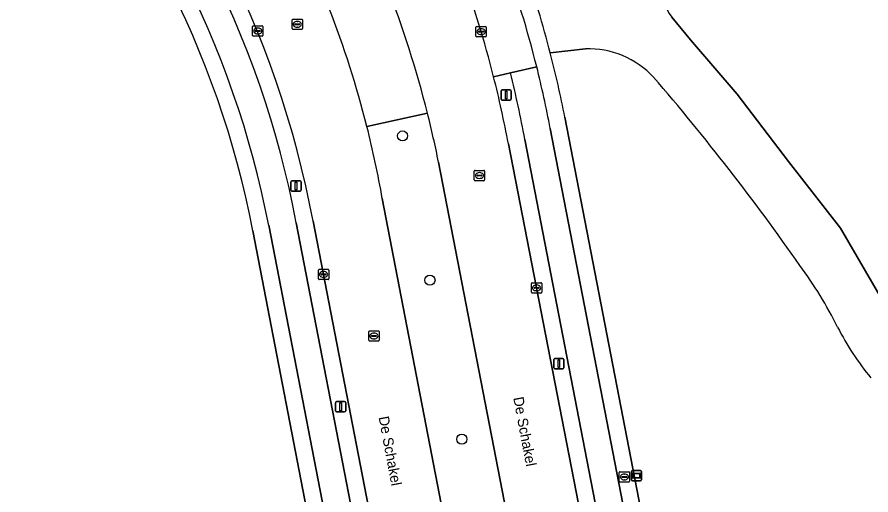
# Model space of a CAD drawing. Extents: x 156141 to 158132, y 385651 to 388333.
# Drawn here: x 156763.2 to 156845.9, y 386839.7 to 386886.1 of the extents above; entities that cross this region are included whole.
import ezdxf

# ---------------------------------------------------------------- set-up
doc = ezdxf.new("R2010")
doc.units = 0
for name, color, linetype in [('IMGEO_Berm_groen', 7, 'Continuous'), ('IMGEO_Boom', 7, 'Continuous'), ('IMGEO_Brandkraan', 7, 'Continuous'), ('IMGEO_Erf', 7, 'Continuous'), ('IMGEO_Fietspad_gesloten', 7, 'Continuous'), ('IMGEO_Kolk', 7, 'Continuous'), ('IMGEO_Lichtmast', 7, 'Continuous'), ('IMGEO_Openbare_ruimte_label', 7, 'Continuous'), ('IMGEO_Rijbaan_lokaal_gesloten', 7, 'Continuous'), ('IMGEO_Rijbaan_lokaal_open', 7, 'Continuous'), ('IMGEO_Rioolput', 7, 'Continuous'), ('IMGEO_Verklikker', 7, 'Continuous'), ('IMGEO_Voetpad_open', 7, 'Continuous')]:
    doc.layers.add(name, color=color, linetype=linetype)

msp = doc.modelspace()

# ---------------------------------------------------------------- linework, layer by layer
at = {"layer": 'IMGEO_Berm_groen'}
for points in [[(156810.993, 386880.684), (156809.365, 386880.309)], [(156802.956, 386876.762), (156797.082, 386875.477)], [(156810.794, 386873.793), (156823.671, 386807.616), (156825.217, 386807.909), (156812.389, 386874.233)], [(156798.576, 386868.484), (156810.203, 386808.253), (156816.188, 386809.335), (156804.032, 386872.006)], [(156790.238, 386866.122), (156802.323, 386803.676), (156803.921, 386803.962), (156791.866, 386866.288)]]:
    msp.add_lwpolyline(points, dxfattribs=at)
for centre, radius, start, end in [((156697.171, 386848.541), 96.344, 10.61478, 43.91153), ((156697.735, 386848.719), 94.126, 10.65483, 44.23031), ((156710.398, 386855.539), 103.69, 10.38669, 14.03443), ((156709.21, 386854.93), 103.32, 10.51953, 14.21947), ((156702.267, 386851.482), 103.814, 11.40228, 14.09375), ((156702.296, 386851.571), 97.754, 9.96341, 14.15559)]:
    msp.add_arc(centre, radius, start, end, dxfattribs=at)
at = {"layer": 'IMGEO_Boom'}
for centre in [(156800.541, 386874.566), (156803.195, 386860.57), (156806.282, 386845.15)]:
    msp.add_circle(centre, 0.489, dxfattribs=at)
at = {"layer": 'IMGEO_Brandkraan'}
for p, q in [((156821.54, 386841.068), (156821.54, 386841.92)), ((156821.615, 386841.994), (156822.467, 386841.994)), ((156821.799, 386841.488), (156821.799, 386841.5)), ((156821.842, 386841.537), (156822.24, 386841.537)), ((156822.028, 386841.774), (156822.053, 386841.774)), ((156822.283, 386841.5), (156822.283, 386841.488)), ((156822.541, 386841.92), (156822.541, 386841.068)), ((156822.467, 386840.994), (156821.615, 386840.994)), ((156822.237, 386841.451), (156821.839, 386841.451)), ((156822.051, 386841.214), (156822.026, 386841.214))]:
    msp.add_line(p, q, dxfattribs=at)
for points in [[(156821.54, 386841.068), (156821.54, 386841.92)], [(156821.615, 386841.994), (156822.467, 386841.994)], [(156822.541, 386841.92), (156822.541, 386841.068)], [(156822.467, 386840.994), (156821.615, 386840.994)]]:
    msp.add_lwpolyline(points, dxfattribs=at)
for centre, radius, start, end in [((156821.617, 386841.918), 0.0765, 91.55205, 178.44795), ((156821.617, 386841.918), 0.0765, 91.55205, 178.44795), ((156821.839, 386841.497), 0.0403, 85.87752, 175.75265), ((156821.836, 386841.487), 0.0366, 178.93798, 274.71019), ((156822.24, 386841.494), 0.043, 264.86636, 352.45326), ((156822.244, 386841.499), 0.0386, 1.73085, 96.63898), ((156822.465, 386841.918), 0.0765, 1.55205, 88.44795), ((156822.465, 386841.918), 0.0765, 1.55205, 88.44795), ((156821.617, 386841.07), 0.0765, 181.55205, 268.44795), ((156821.617, 386841.07), 0.0765, 181.55205, 268.44795), ((156822.465, 386841.07), 0.0765, 271.55205, 358.44795), ((156822.465, 386841.07), 0.0765, 271.55205, 358.44795)]:
    msp.add_arc(centre, radius, start, end, dxfattribs=at)
for centre, major_axis, ratio, start_param, end_param in [((156822.027, 386841.494), (-0.387, 0.002), 0.722429, 4.712389, 7.853982), ((156822.052, 386841.494), (-0.39, 0.002), 0.717154, 1.570796, 4.712389)]:
    msp.add_ellipse(centre, major_axis=major_axis, ratio=ratio, start_param=start_param, end_param=end_param, dxfattribs=at)
at = {"layer": 'IMGEO_Erf'}
for points in [[(156826.636, 386886.092), (156828.456, 386883.873), (156832.982, 386878.607), (156837.967, 386872.098), (156842.982, 386865.604), (156848.662, 386855.9)], [(156818.263, 386883.015), (156814.86, 386882.608)], [(156816.275, 386876.382), (156829.265, 386809.226), (156830.26, 386804.068), (156832.909, 386790.329), (156833.43, 386787.629), (156834.864, 386780.192), (156835.335, 386777.724), (156835.579, 386776.447), (156836.335, 386772.49), (156839.986, 386753.519), (156840.741, 386750), (156841.955, 386745.365)], [(156789.25, 386785.838), (156797.816, 386791.602), (156799.862, 386793.67), (156786.023, 386865.361)]]:
    msp.add_lwpolyline(points, dxfattribs=at)
for centre, radius, start, end in [((156696.676, 386848.251), 90.971, 10.84103, 44.16358), ((156830.262, 386888.804), 4.528, 133.86718, 216.79599), ((156818.511, 386874.287), 8.732, 43.19971, 91.62579), ((156711.598, 386855.865), 106.669, 11.08926, 14.51927), ((156650.564, 386730.314), 229.935, 34.94261, 40.70341), ((156805.973, 386837.682), 41.058, 26.50354, 36.33706), ((156866.609, 386868.18), 26.816, 207.00334, 219.5816)]:
    msp.add_arc(centre, radius, start, end, dxfattribs=at)
at = {"layer": 'IMGEO_Fietspad_gesloten'}
for points in [[(156813.544, 386881.272), (156810.993, 386880.684)], [(156827.767, 386808.488), (156814.851, 386875.299)], [(156812.389, 386874.233), (156825.217, 386807.909), (156825.43, 386807.901), (156825.634, 386806.897), (156826.277, 386803.502), (156826.472, 386802.55), (156826.249, 386802.491), (156828.033, 386793.229)], [(156787.566, 386865.893), (156800.014, 386801.586), (156802.367, 386802.045), (156802.289, 386802.533), (156802.117, 386803.516), (156802.323, 386803.676), (156790.238, 386866.122)]]:
    msp.add_lwpolyline(points, dxfattribs=at)
for centre, radius, start, end in [((156697.735, 386848.719), 94.126, 10.65483, 44.23031), ((156696.985, 386848.39), 92.256, 10.93627, 43.98113), ((156711.691, 386855.855), 104.977, 10.67398, 14.01163), ((156710.398, 386855.539), 103.69, 10.38669, 14.03443)]:
    msp.add_arc(centre, radius, start, end, dxfattribs=at)
at = {"layer": 'IMGEO_Kolk'}
for p, q in [((156786.008, 386884.32), (156786.008, 386885.172)), ((156786.083, 386885.246), (156786.935, 386885.246)), ((156786.267, 386884.74), (156786.267, 386884.752)), ((156786.705, 386884.703), (156786.307, 386884.703)), ((156786.31, 386884.789), (156786.708, 386884.789)), ((156786.496, 386885.026), (156786.521, 386885.026)), ((156786.751, 386884.752), (156786.751, 386884.74)), ((156787.009, 386885.172), (156787.009, 386884.32)), ((156807.654, 386884.252), (156807.654, 386885.104)), ((156807.729, 386885.178), (156808.581, 386885.178)), ((156807.913, 386884.672), (156807.913, 386884.684)), ((156808.351, 386884.635), (156807.953, 386884.635)), ((156807.956, 386884.721), (156808.354, 386884.721)), ((156808.142, 386884.958), (156808.167, 386884.958)), ((156808.397, 386884.684), (156808.397, 386884.672)), ((156808.655, 386885.104), (156808.655, 386884.252)), ((156786.935, 386884.246), (156786.083, 386884.246)), ((156786.519, 386884.466), (156786.494, 386884.466)), ((156808.581, 386884.178), (156807.729, 386884.178)), ((156808.165, 386884.398), (156808.14, 386884.398)), ((156792.385, 386860.705), (156792.385, 386861.557)), ((156792.46, 386861.631), (156793.312, 386861.631)), ((156792.873, 386861.411), (156792.898, 386861.411)), ((156793.386, 386861.557), (156793.386, 386860.705)), ((156793.312, 386860.631), (156792.46, 386860.631)), ((156792.644, 386861.125), (156792.644, 386861.137)), ((156793.082, 386861.088), (156792.684, 386861.088)), ((156792.687, 386861.174), (156793.085, 386861.174)), ((156792.896, 386860.851), (156792.871, 386860.851)), ((156793.128, 386861.137), (156793.128, 386861.125)), ((156813.032, 386859.401), (156813.032, 386860.253)), ((156813.107, 386860.327), (156813.959, 386860.327)), ((156813.291, 386859.821), (156813.291, 386859.833)), ((156813.729, 386859.784), (156813.331, 386859.784)), ((156813.334, 386859.87), (156813.732, 386859.87)), ((156813.52, 386860.107), (156813.545, 386860.107)), ((156813.775, 386859.833), (156813.775, 386859.821)), ((156814.033, 386860.253), (156814.033, 386859.401)), ((156813.959, 386859.327), (156813.107, 386859.327)), ((156813.543, 386859.547), (156813.518, 386859.547))]:
    msp.add_line(p, q, dxfattribs=at)
for points in [[(156786.008, 386884.32), (156786.008, 386885.172)], [(156786.083, 386885.246), (156786.935, 386885.246)], [(156787.009, 386885.172), (156787.009, 386884.32)], [(156807.654, 386884.252), (156807.654, 386885.104)], [(156807.729, 386885.178), (156808.581, 386885.178)], [(156808.655, 386885.104), (156808.655, 386884.252)], [(156786.935, 386884.246), (156786.083, 386884.246)], [(156808.581, 386884.178), (156807.729, 386884.178)], [(156792.385, 386860.705), (156792.385, 386861.557)], [(156792.46, 386861.631), (156793.312, 386861.631)], [(156793.386, 386861.557), (156793.386, 386860.705)], [(156793.312, 386860.631), (156792.46, 386860.631)], [(156813.032, 386859.401), (156813.032, 386860.253)], [(156813.107, 386860.327), (156813.959, 386860.327)], [(156814.033, 386860.253), (156814.033, 386859.401)], [(156813.959, 386859.327), (156813.107, 386859.327)]]:
    msp.add_lwpolyline(points, dxfattribs=at)
for centre, radius, start, end in [((156786.085, 386885.17), 0.0765, 91.55205, 178.44795), ((156786.085, 386885.17), 0.0765, 91.55205, 178.44795), ((156786.307, 386884.749), 0.0403, 85.87752, 175.75265), ((156786.304, 386884.739), 0.0366, 178.93798, 274.71019), ((156786.708, 386884.746), 0.043, 264.86636, 352.45326), ((156786.712, 386884.751), 0.0386, 1.73085, 96.63898), ((156786.933, 386885.17), 0.0765, 1.55205, 88.44795), ((156786.933, 386885.17), 0.0765, 1.55205, 88.44795), ((156807.731, 386885.102), 0.0765, 91.55205, 178.44795), ((156807.731, 386885.102), 0.0765, 91.55205, 178.44795), ((156807.953, 386884.681), 0.0403, 85.87752, 175.75265), ((156807.95, 386884.671), 0.0366, 178.93798, 274.71019), ((156808.354, 386884.678), 0.043, 264.86636, 352.45326), ((156808.358, 386884.683), 0.0386, 1.73085, 96.63898), ((156808.579, 386885.102), 0.0765, 1.55205, 88.44795), ((156808.579, 386885.102), 0.0765, 1.55205, 88.44795), ((156786.085, 386884.322), 0.0765, 181.55205, 268.44795), ((156786.085, 386884.322), 0.0765, 181.55205, 268.44795), ((156786.933, 386884.322), 0.0765, 271.55205, 358.44795), ((156786.933, 386884.322), 0.0765, 271.55205, 358.44795), ((156807.731, 386884.254), 0.0765, 181.55205, 268.44795), ((156807.731, 386884.254), 0.0765, 181.55205, 268.44795), ((156808.579, 386884.254), 0.0765, 271.55205, 358.44795), ((156808.579, 386884.254), 0.0765, 271.55205, 358.44795), ((156792.462, 386861.555), 0.0765, 91.55205, 178.44795), ((156792.462, 386861.555), 0.0765, 91.55205, 178.44795), ((156793.31, 386861.555), 0.0765, 1.55205, 88.44795), ((156793.31, 386861.555), 0.0765, 1.55205, 88.44795), ((156792.462, 386860.707), 0.0765, 181.55205, 268.44795), ((156792.462, 386860.707), 0.0765, 181.55205, 268.44795), ((156792.684, 386861.134), 0.0403, 85.87752, 175.75265), ((156792.681, 386861.124), 0.0366, 178.93798, 274.71019), ((156793.085, 386861.131), 0.043, 264.86636, 352.45326), ((156793.089, 386861.136), 0.0386, 1.73085, 96.63898), ((156793.31, 386860.707), 0.0765, 271.55205, 358.44795), ((156793.31, 386860.707), 0.0765, 271.55205, 358.44795), ((156813.109, 386860.251), 0.0765, 91.55205, 178.44795), ((156813.109, 386860.251), 0.0765, 91.55205, 178.44795), ((156813.331, 386859.83), 0.0403, 85.87752, 175.75265), ((156813.328, 386859.82), 0.0366, 178.93798, 274.71019), ((156813.732, 386859.827), 0.043, 264.86636, 352.45326), ((156813.736, 386859.832), 0.0386, 1.73085, 96.63898), ((156813.957, 386860.251), 0.0765, 1.55205, 88.44795), ((156813.957, 386860.251), 0.0765, 1.55205, 88.44795), ((156813.109, 386859.403), 0.0765, 181.55205, 268.44795), ((156813.109, 386859.403), 0.0765, 181.55205, 268.44795), ((156813.957, 386859.403), 0.0765, 271.55205, 358.44795), ((156813.957, 386859.403), 0.0765, 271.55205, 358.44795)]:
    msp.add_arc(centre, radius, start, end, dxfattribs=at)
for centre, major_axis, ratio, start_param, end_param in [((156786.495, 386884.746), (-0.387, 0.002), 0.722429, 4.712389, 7.853982), ((156786.52, 386884.746), (-0.39, 0.002), 0.717154, 1.570796, 4.712389), ((156808.141, 386884.678), (-0.387, 0.002), 0.722429, 4.712389, 7.853982), ((156808.166, 386884.678), (-0.39, 0.002), 0.717154, 1.570796, 4.712389), ((156792.872, 386861.131), (-0.387, 0.002), 0.722429, 4.712389, 7.853982), ((156792.897, 386861.131), (-0.39, 0.002), 0.717154, 1.570796, 4.712389), ((156813.519, 386859.827), (-0.387, 0.002), 0.722429, 4.712389, 7.853982), ((156813.544, 386859.827), (-0.39, 0.002), 0.717154, 1.570796, 4.712389)]:
    msp.add_ellipse(centre, major_axis=major_axis, ratio=ratio, start_param=start_param, end_param=end_param, dxfattribs=at)
at = {"layer": 'IMGEO_Lichtmast'}
for p, q in [((156810.083, 386878.137), (156810.083, 386878.937)), ((156810.083, 386878.937), (156810.083, 386878.137)), ((156810.183, 386879.037), (156810.973, 386879.037)), ((156810.973, 386879.037), (156810.183, 386879.037)), ((156811.073, 386878.937), (156811.073, 386878.137)), ((156811.073, 386878.137), (156811.073, 386878.937)), ((156810.973, 386878.037), (156810.183, 386878.037)), ((156810.183, 386878.037), (156810.973, 386878.037)), ((156789.712, 386869.299), (156789.712, 386870.099)), ((156789.712, 386870.099), (156789.712, 386869.299)), ((156789.812, 386870.199), (156790.602, 386870.199)), ((156790.602, 386870.199), (156789.812, 386870.199)), ((156790.702, 386870.099), (156790.702, 386869.299)), ((156790.702, 386869.299), (156790.702, 386870.099)), ((156790.602, 386869.199), (156789.812, 386869.199)), ((156789.812, 386869.199), (156790.602, 386869.199)), ((156815.191, 386852.066), (156815.191, 386852.866)), ((156815.191, 386852.866), (156815.191, 386852.066)), ((156815.291, 386852.966), (156816.081, 386852.966)), ((156816.081, 386852.966), (156815.291, 386852.966)), ((156816.181, 386852.866), (156816.181, 386852.066)), ((156816.181, 386852.066), (156816.181, 386852.866)), ((156816.081, 386851.966), (156815.291, 386851.966)), ((156815.291, 386851.966), (156816.081, 386851.966)), ((156794.036, 386847.893), (156794.036, 386848.693)), ((156794.036, 386848.693), (156794.036, 386847.893)), ((156794.136, 386848.793), (156794.926, 386848.793)), ((156794.926, 386848.793), (156794.136, 386848.793)), ((156795.026, 386848.693), (156795.026, 386847.893)), ((156795.026, 386847.893), (156795.026, 386848.693)), ((156794.926, 386847.793), (156794.136, 386847.793)), ((156794.136, 386847.793), (156794.926, 386847.793))]:
    msp.add_line(p, q, dxfattribs=at)
for points in [[(156810.503, 386878.912), (156810.653, 386878.912), (156810.653, 386878.162), (156810.503, 386878.162), (156810.503, 386878.912)], [(156790.132, 386870.074), (156790.282, 386870.074), (156790.282, 386869.324), (156790.132, 386869.324), (156790.132, 386870.074)], [(156815.611, 386852.841), (156815.761, 386852.841), (156815.761, 386852.091), (156815.611, 386852.091), (156815.611, 386852.841)], [(156794.456, 386848.668), (156794.606, 386848.668), (156794.606, 386847.918), (156794.456, 386847.918), (156794.456, 386848.668)]]:
    msp.add_lwpolyline(points, dxfattribs=at)
for centre, start, end in [((156810.183, 386878.937), 90, 180), ((156810.183, 386878.937), 90, 180), ((156810.973, 386878.937), 0, 90), ((156810.973, 386878.937), 360, 90), ((156810.183, 386878.137), 180, 270), ((156810.183, 386878.137), 180, 270), ((156810.973, 386878.137), 270, 0), ((156810.973, 386878.137), 270, 0), ((156789.812, 386870.099), 90, 180), ((156789.812, 386870.099), 90, 180), ((156790.602, 386870.099), 0, 90), ((156790.602, 386870.099), 360, 90), ((156789.812, 386869.299), 180, 270), ((156789.812, 386869.299), 180, 270), ((156790.602, 386869.299), 270, 0), ((156790.602, 386869.299), 270, 0), ((156815.291, 386852.866), 90, 180), ((156815.291, 386852.866), 90, 180), ((156816.081, 386852.866), 0, 90), ((156816.081, 386852.866), 360, 90), ((156815.291, 386852.066), 180, 270), ((156815.291, 386852.066), 180, 270), ((156816.081, 386852.066), 270, 0), ((156816.081, 386852.066), 270, 0), ((156794.136, 386848.693), 90, 180), ((156794.136, 386848.693), 90, 180), ((156794.926, 386848.693), 0, 90), ((156794.926, 386848.693), 360, 90), ((156794.136, 386847.893), 180, 270), ((156794.136, 386847.893), 180, 270), ((156794.926, 386847.893), 270, 0), ((156794.926, 386847.893), 270, 0)]:
    msp.add_arc(centre, 0.1, start, end, dxfattribs=at)
at = {"layer": 'IMGEO_Rijbaan_lokaal_gesloten'}
for points in [[(156804.032, 386872.006), (156816.188, 386809.335), (156816.77, 386806.337), (156817, 386805.151), (156823.89, 386806.503), (156823.671, 386807.616), (156810.794, 386873.793)], [(156791.866, 386866.288), (156803.921, 386803.962), (156804.129, 386802.843), (156811.016, 386804.05), (156810.792, 386805.205), (156810.203, 386808.253), (156798.576, 386868.484)]]:
    msp.add_lwpolyline(points, dxfattribs=at)
for centre, radius, start, end in [((156697.171, 386848.541), 96.344, 10.61478, 43.91153), ((156709.441, 386854.985), 103.083, 14.22096, 20.0977), ((156702.571, 386851.552), 103.502, 14.09743, 21.30467), ((156703.2, 386851.742), 96.836, 14.18776, 21.33413), ((156709.21, 386854.93), 103.32, 10.51953, 14.21947), ((156702.267, 386851.482), 103.814, 11.40228, 14.09375), ((156702.296, 386851.571), 97.754, 9.96341, 14.15559)]:
    msp.add_arc(centre, radius, start, end, dxfattribs=at)
at = {"layer": 'IMGEO_Rijbaan_lokaal_open'}
for points in [[(156848.662, 386855.9), (156842.982, 386865.604), (156837.967, 386872.098), (156832.982, 386878.607), (156828.456, 386883.873), (156826.636, 386886.092)], [(156814.86, 386882.608), (156818.263, 386883.015)], [(156809.365, 386880.309), (156810.993, 386880.684), (156813.544, 386881.272)], [(156797.082, 386875.477), (156802.956, 386876.762)]]:
    msp.add_lwpolyline(points, dxfattribs=at)
for centre, radius, start, end in [((156830.262, 386888.804), 4.528, 133.86718, 216.79599), ((156710.397, 386855.529), 106.31, 14.0134, 19.91092), ((156709.441, 386854.985), 103.083, 14.22096, 20.0977), ((156711.519, 386855.915), 106.733, 14.4829, 19.05231), ((156702.571, 386851.552), 103.502, 14.09743, 21.30467), ((156703.2, 386851.742), 96.836, 14.18776, 21.33413), ((156818.511, 386874.287), 8.732, 43.19971, 91.62579), ((156650.564, 386730.314), 229.935, 34.94261, 40.70341), ((156805.973, 386837.682), 41.058, 26.50354, 36.33706), ((156866.609, 386868.18), 26.816, 207.00334, 219.5816)]:
    msp.add_arc(centre, radius, start, end, dxfattribs=at)
at = {"layer": 'IMGEO_Rioolput'}
for p, q in [((156789.834, 386884.968), (156789.834, 386885.82)), ((156789.909, 386885.894), (156790.761, 386885.894)), ((156790.093, 386885.388), (156790.093, 386885.4)), ((156790.531, 386885.351), (156790.133, 386885.351)), ((156790.136, 386885.437), (156790.534, 386885.437)), ((156790.322, 386885.674), (156790.347, 386885.674)), ((156790.577, 386885.4), (156790.577, 386885.388)), ((156790.835, 386885.82), (156790.835, 386884.968)), ((156790.761, 386884.894), (156789.909, 386884.894)), ((156790.345, 386885.114), (156790.32, 386885.114)), ((156807.496, 386870.298), (156807.496, 386871.15)), ((156807.571, 386871.224), (156808.423, 386871.224)), ((156807.755, 386870.718), (156807.755, 386870.73)), ((156808.193, 386870.681), (156807.795, 386870.681)), ((156807.798, 386870.767), (156808.196, 386870.767)), ((156808.007, 386870.444), (156807.982, 386870.444)), ((156807.984, 386871.004), (156808.009, 386871.004)), ((156808.239, 386870.73), (156808.239, 386870.718)), ((156808.497, 386871.15), (156808.497, 386870.298)), ((156808.423, 386870.224), (156807.571, 386870.224)), ((156797.265, 386854.74), (156797.265, 386855.592)), ((156797.34, 386855.666), (156798.192, 386855.666)), ((156798.266, 386855.592), (156798.266, 386854.74)), ((156797.524, 386855.16), (156797.524, 386855.172)), ((156797.962, 386855.123), (156797.564, 386855.123)), ((156797.567, 386855.209), (156797.965, 386855.209)), ((156797.776, 386854.886), (156797.751, 386854.886)), ((156797.753, 386855.446), (156797.778, 386855.446)), ((156798.008, 386855.172), (156798.008, 386855.16)), ((156798.192, 386854.666), (156797.34, 386854.666))]:
    msp.add_line(p, q, dxfattribs=at)
for points in [[(156789.834, 386884.968), (156789.834, 386885.82)], [(156789.909, 386885.894), (156790.761, 386885.894)], [(156790.835, 386885.82), (156790.835, 386884.968)], [(156790.761, 386884.894), (156789.909, 386884.894)], [(156807.496, 386870.298), (156807.496, 386871.15)], [(156807.571, 386871.224), (156808.423, 386871.224)], [(156808.497, 386871.15), (156808.497, 386870.298)], [(156808.423, 386870.224), (156807.571, 386870.224)], [(156797.265, 386854.74), (156797.265, 386855.592)], [(156797.34, 386855.666), (156798.192, 386855.666)], [(156798.266, 386855.592), (156798.266, 386854.74)], [(156798.192, 386854.666), (156797.34, 386854.666)]]:
    msp.add_lwpolyline(points, dxfattribs=at)
for centre, radius, start, end in [((156789.911, 386885.818), 0.0765, 91.55205, 178.44795), ((156789.911, 386885.818), 0.0765, 91.55205, 178.44795), ((156790.133, 386885.397), 0.0403, 85.87752, 175.75265), ((156790.13, 386885.387), 0.0366, 178.93798, 274.71019), ((156790.534, 386885.394), 0.043, 264.86636, 352.45326), ((156790.538, 386885.399), 0.0386, 1.73085, 96.63898), ((156790.759, 386885.818), 0.0765, 1.55205, 88.44795), ((156790.759, 386885.818), 0.0765, 1.55205, 88.44795), ((156789.911, 386884.97), 0.0765, 181.55205, 268.44795), ((156789.911, 386884.97), 0.0765, 181.55205, 268.44795), ((156790.759, 386884.97), 0.0765, 271.55205, 358.44795), ((156790.759, 386884.97), 0.0765, 271.55205, 358.44795), ((156807.573, 386871.148), 0.0765, 91.55205, 178.44795), ((156807.573, 386871.148), 0.0765, 91.55205, 178.44795), ((156807.795, 386870.727), 0.0403, 85.87752, 175.75265), ((156807.792, 386870.717), 0.0366, 178.93798, 274.71019), ((156808.196, 386870.724), 0.043, 264.86636, 352.45326), ((156808.2, 386870.729), 0.0386, 1.73085, 96.63898), ((156808.421, 386871.148), 0.0765, 1.55205, 88.44795), ((156808.421, 386871.148), 0.0765, 1.55205, 88.44795), ((156807.573, 386870.3), 0.0765, 181.55205, 268.44795), ((156807.573, 386870.3), 0.0765, 181.55205, 268.44795), ((156808.421, 386870.3), 0.0765, 271.55205, 358.44795), ((156808.421, 386870.3), 0.0765, 271.55205, 358.44795), ((156797.342, 386855.59), 0.0765, 91.55205, 178.44795), ((156797.342, 386855.59), 0.0765, 91.55205, 178.44795), ((156798.19, 386855.59), 0.0765, 1.55205, 88.44795), ((156798.19, 386855.59), 0.0765, 1.55205, 88.44795), ((156797.342, 386854.742), 0.0765, 181.55205, 268.44795), ((156797.342, 386854.742), 0.0765, 181.55205, 268.44795), ((156797.564, 386855.169), 0.0403, 85.87752, 175.75265), ((156797.561, 386855.159), 0.0366, 178.93798, 274.71019), ((156797.965, 386855.166), 0.043, 264.86636, 352.45326), ((156797.969, 386855.171), 0.0386, 1.73085, 96.63898), ((156798.19, 386854.742), 0.0765, 271.55205, 358.44795), ((156798.19, 386854.742), 0.0765, 271.55205, 358.44795)]:
    msp.add_arc(centre, radius, start, end, dxfattribs=at)
for centre, major_axis, ratio, start_param, end_param in [((156790.321, 386885.394), (-0.387, 0.002), 0.722429, 4.712389, 7.853982), ((156790.346, 386885.394), (-0.39, 0.002), 0.717154, 1.570796, 4.712389), ((156807.983, 386870.724), (-0.387, 0.002), 0.722429, 4.712389, 7.853982), ((156808.008, 386870.724), (-0.39, 0.002), 0.717154, 1.570796, 4.712389), ((156797.752, 386855.166), (-0.387, 0.002), 0.722429, 4.712389, 7.853982), ((156797.777, 386855.166), (-0.39, 0.002), 0.717154, 1.570796, 4.712389)]:
    msp.add_ellipse(centre, major_axis=major_axis, ratio=ratio, start_param=start_param, end_param=end_param, dxfattribs=at)
at = {"layer": 'IMGEO_Verklikker'}
for p, q in [((156822.717, 386841.217), (156822.717, 386842.017)), ((156822.717, 386842.017), (156822.717, 386841.217)), ((156822.817, 386842.117), (156823.607, 386842.117)), ((156823.607, 386842.117), (156822.817, 386842.117)), ((156823.707, 386842.017), (156823.707, 386841.217)), ((156823.707, 386841.217), (156823.707, 386842.017)), ((156823.607, 386841.117), (156822.817, 386841.117)), ((156822.817, 386841.117), (156823.607, 386841.117))]:
    msp.add_line(p, q, dxfattribs=at)
for points in [[(156822.818, 386841.849), (156823.606, 386841.849), (156823.606, 386841.385), (156822.818, 386841.385), (156822.818, 386841.849)], [(156822.883, 386841.784), (156822.883, 386841.45), (156823.541, 386841.45), (156823.541, 386841.784), (156822.883, 386841.784)]]:
    msp.add_lwpolyline(points, dxfattribs=at)
for centre, start, end in [((156822.817, 386842.017), 90, 180), ((156822.817, 386842.017), 90, 180), ((156823.607, 386842.017), 0, 90), ((156823.607, 386842.017), 360, 90), ((156822.817, 386841.217), 180, 270), ((156822.817, 386841.217), 180, 270), ((156823.607, 386841.217), 270, 0), ((156823.607, 386841.217), 270, 0)]:
    msp.add_arc(centre, 0.1, start, end, dxfattribs=at)
at = {"layer": 'IMGEO_Voetpad_open'}
for points in [[(156814.851, 386875.299), (156827.767, 386808.488), (156831.327, 386790.024), (156832.909, 386790.329), (156830.26, 386804.068), (156829.265, 386809.226), (156816.275, 386876.382)], [(156786.023, 386865.361), (156799.862, 386793.67), (156800.502, 386790.354), (156801.763, 386791.359), (156801.853, 386791.693), (156800.014, 386801.586), (156787.566, 386865.893)]]:
    msp.add_lwpolyline(points, dxfattribs=at)
for centre, radius, start, end in [((156696.985, 386848.39), 92.256, 10.93627, 43.98113), ((156696.676, 386848.251), 90.971, 10.84103, 44.16358), ((156710.397, 386855.529), 106.31, 14.0134, 19.91092), ((156711.519, 386855.915), 106.733, 14.4829, 19.05231), ((156711.598, 386855.865), 106.669, 11.08926, 14.51927), ((156711.691, 386855.855), 104.977, 10.67398, 14.01163)]:
    msp.add_arc(centre, radius, start, end, dxfattribs=at)

# ---------------------------------------------------------------- texts
at = {"layer": 'IMGEO_Openbare_ruimte_label'}
for p in [(156811.263, 386849.165), (156798.21, 386847.283)]:
    msp.add_text('De Schakel', height=1, rotation=280.65836, dxfattribs=at).set_placement(p)

doc.saveas('drawing.dxf')
